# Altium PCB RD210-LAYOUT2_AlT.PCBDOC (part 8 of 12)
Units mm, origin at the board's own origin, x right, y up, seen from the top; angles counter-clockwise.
Board outline 250 x 123 mm, 4 copper layers (TOP, Mid-Layer 1, Mid-Layer 2, BOTTOM), stack 0.711 mm thick; 1043 components, 659 nets, 2786 pads, 1228 vias.
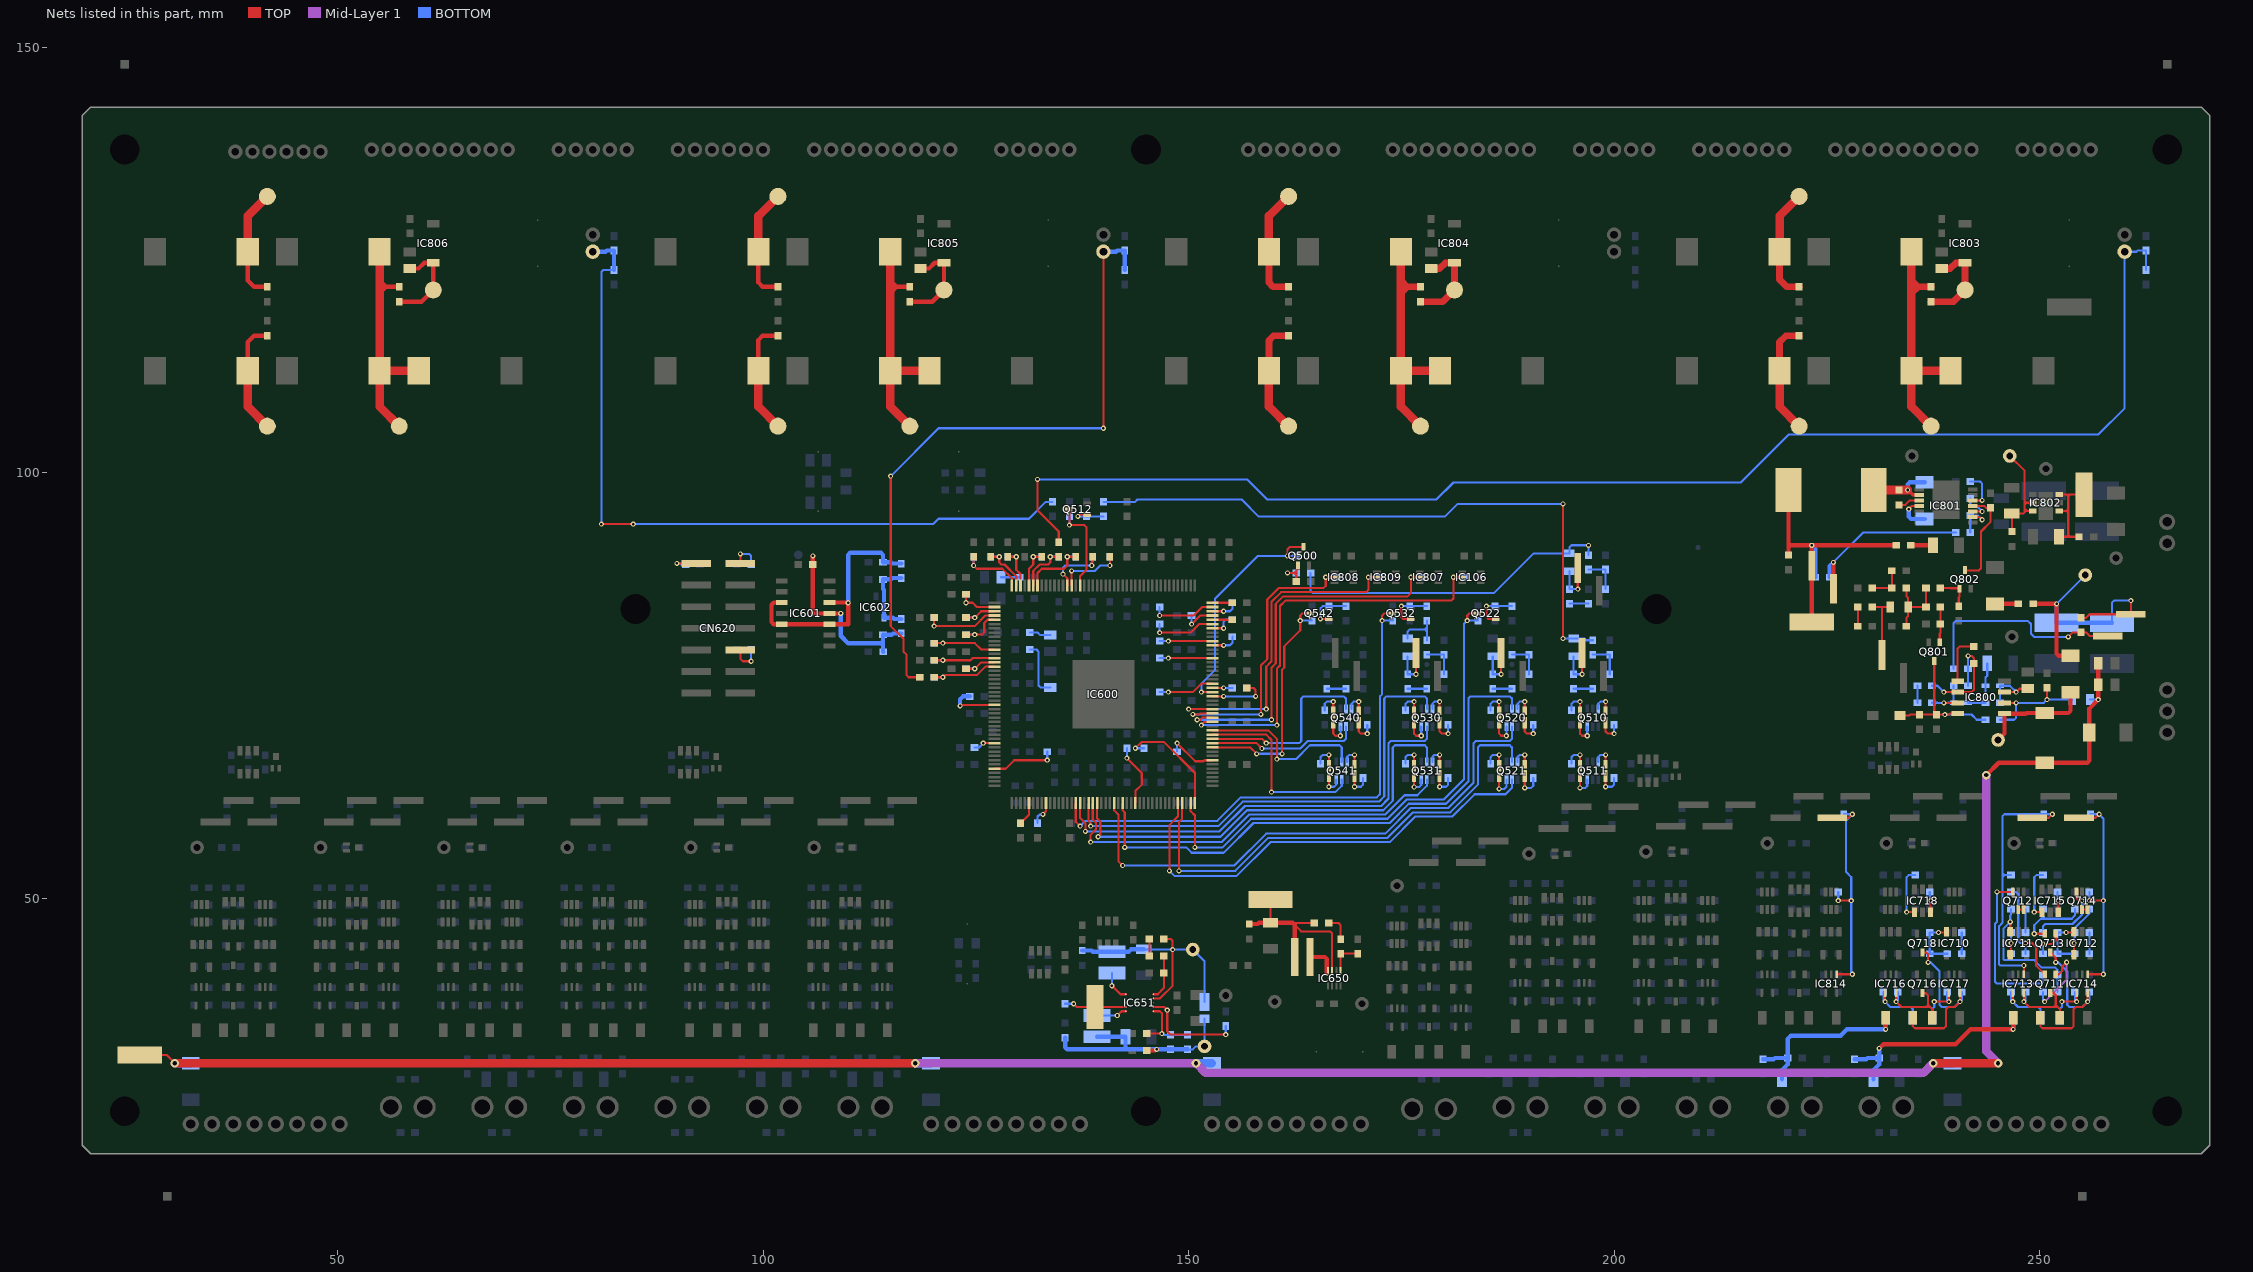
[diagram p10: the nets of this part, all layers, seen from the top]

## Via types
v1: diameter 0.6, hole 0.3, TOP to BOTTOM, 1134 vias
v2: diameter 1, hole 0.5, TOP to BOTTOM, 94 vias

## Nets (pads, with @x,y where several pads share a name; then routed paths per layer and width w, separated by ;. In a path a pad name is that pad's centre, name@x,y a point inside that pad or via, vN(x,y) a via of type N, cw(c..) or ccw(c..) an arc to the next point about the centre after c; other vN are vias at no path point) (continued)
N00100041: Q542.1 R597.2 R598.2 | length 5.3
  TOP w0.25: v1(165.5,82.85) Q542.1@166.425,82.85
  BOTTOM w0.25: v1(165.5,82.85) 165.5,84.1 165.75,84.35 R598.2@166.5,84.35 R597.2@168.5,84.35
N00100042: C520.2 IC600.42 R520.1 | length 5.6
  TOP w0.25: R520.1@128.75,90.15 v1(129.75,90.15) 129.75,88.625 130.25,88.125 IC600.42@130.25,86.8
  BOTTOM w0.25: C520.2@128.75,90.15 v1(129.75,90.15)
N00100043: C521.1 IC600.47 R521.2 | length 4.7
  TOP w0.25: R521.2@123.85,83 v1(124.875,83) 125.625,83.75 IC600.47@127.2,83.75
  BOTTOM w0.25: C521.1@123.85,83 v1(124.875,83)
N00100044: C532.2 IC600.31 R532.2 | length 7.9
  TOP w0.25: v1(135.25,88.125) 135.75,87.625 IC600.31@135.75,86.8 ; v1(138.625,89.125) 138.625,89.5 138.75,89.625 R532.2@138.75,90.15
  BOTTOM w0.25: v1(135.25,88.125) 135.25,88.875 135.5,89.125 v1(138.625,89.125) 138.625,89.5 138.75,89.625 C532.2@138.75,90.15
N00100045: C533.1 IC600.58 R533.2 | length 8.2
  TOP w0.25: R533.2@120.1,78 v1(121.125,78) 124.375,78 124.625,78.25 IC600.58@127.2,78.25
  BOTTOM w0.25: C533.1@120.1,78 v1(121.125,78)
N00100047: C531.1 IC600.48 R531.2 | length 9.6
  TOP w0.25: R531.2@120.1,83 v1(120.1,82) 124.875,82 126.125,83.25 IC600.48@127.2,83.25
  BOTTOM w0.25: v1(120.1,82) C531.1@120.1,83
N00100048: C542.2 IC600.30 R542.2 | length 8.5
  TOP w0.25: IC600.30@136.25,86.8 v1(136.25,88.5) ; v1(140.75,89.125) R542.2@140.75,90.15
  BOTTOM w0.25: v1(136.25,88.5) 139,88.5 139.625,89.125 v1(140.75,89.125) C542.2@140.75,90.15
N00100049: C543.1 IC600.59 R543.2 | length 4.7
  TOP w0.25: R543.2@123.85,77 v1(124.875,77) 125.625,77.75 IC600.59@127.2,77.75
  BOTTOM w0.25: C543.1@123.85,77 v1(124.875,77)
N00100050: C540.2 IC600.40 R540.1 | length 5.6
  TOP w0.25: IC600.40@131.25,86.8 131.25,88.75 131.75,89.25 v1(131.75,90.15) R540.1@132.75,90.15
  BOTTOM w0.25: v1(131.75,90.15) C540.2@132.75,90.15
N00100051: C541.1 IC600.49 R541.2 | length 5.8
  TOP w0.25: R541.2@123.85,81 v1(124.875,81) 125.75,81 126,81.25 126,82.375 126.375,82.75 IC600.49@127.2,82.75
  BOTTOM w0.25: C541.1@123.85,81 v1(124.875,81)
N00100052: C511.1 IC600.46 R511.2 | length 5.6
  TOP w0.25: R511.2@123.85,85.75 v1(123.85,84.75) 124.625,84.75 125.125,84.25 IC600.46@127.2,84.25
  BOTTOM w0.25: v1(123.85,84.75) C511.1@123.85,85.75
N00100053: C510.2 IC600.43 R510.1 | length 6.4
  TOP w0.25: R510.1@126.75,90.15 v1(127.75,90.15) 127.75,89.5 128,89.25 128.375,89.25 129.75,87.875 IC600.43@129.75,86.8
  BOTTOM w0.25: C510.2@126.75,90.15 v1(127.75,90.15)
N00100055: C513.1 IC600.56 R513.2 | length 8.4
  TOP w0.25: R513.2@120.1,80 v1(121.125,80) 124.875,80 125.625,79.25 IC600.56@127.2,79.25
  BOTTOM w0.25: C513.1@120.1,80 v1(121.125,80)
N00100057: C512.2 IC600.44 R512.1 | length 8
  TOP w0.25: R512.1@124.75,90.15 v1(124.75,89.125) 125.125,88.75 128.125,88.75 129.25,87.625 IC600.44@129.25,86.8
  BOTTOM w0.25: v1(124.75,89.125) C512.2@124.75,90.15
N00100061: C544.2 CN305.1 R592.2 R593.1 | length 90.2
  TOP w0.25: v1(81,94) v1(84.75,94)
  BOTTOM w0.25: v1(81,94) 81,123.625 81.225,123.85 R592.2@82.5,123.85 ; v1(84.75,94) 120,94 120.625,94.625 131.25,94.625 133.225,96.6 R593.1@134,96.6
  BOTTOM w0.5: CN305.1@80,126 81.475,126 81.625,126.15 C544.2@82.5,126.15 R592.2@82.5,123.85
N00100071: IC600.69 R613.1 | length 6.1
  TOP w0.25: v1(123.15,72.625) 123.275,72.75 IC600.69@127.2,72.75
  BOTTOM w0.5: v1(123.15,72.625) 123.15,73.4 123.5,73.75 R613.1@124.275,73.75
N00100083: IC600.142 Q542.3 R599.1 | length 28.3
  TOP w0.25: IC600.142@152.8,67.75 157.25,67.75 v1(158,67) ; v1(161,67) 161,76.875 161.25,77.125 161.25,79.625 163.125,81.5 v1(163.125,82.65) 163.125,83.25 163.375,83.5 Q542.3@164.275,83.5 Q542.3@164.325,83.5
  BOTTOM w0.25: v1(158,67) v1(161,67) ; v1(163.125,82.65) R599.1@164.5,82.65
N00100086: DS511.2 Q510.3 | length 3.1
  TOP w0.25: DS511.2@196,70.45 196,69.375 196.25,69.125 v1(196.85,69.125)
  BOTTOM w0.25: v1(196.85,69.125) Q510.3@196.85,70.225
N00100087: IC106.2 IC600.148 R648.1 | length 50
  TOP w0.25: v1(151.5,70.375) 151.875,70.75 IC600.148@152.8,70.75 ; v1(160.375,70.375) 160.375,77 160.75,77.375 160.75,84.375 161.375,85 180.875,85 181.125,85.25 v1(181.125,87.75) IC106.2@182.15,87.75
  BOTTOM w0.25: v1(151.5,70.375) v1(160.375,70.375) ; v1(181.125,87.75) R648.1@182.4,87.75
N00100091: C546.1 C547.2 | length 2.3
  BOTTOM w0.25: C546.1@166.25,74.65 C547.2@168.5,74.65
N00100092: C500.2 CN500.1 R501.1 | length 5.6
  TOP w0.25: CN500.1@195.73,88.85 195.73,86.37 v1(195.75,86.35)
  BOTTOM w0.25: R501.1@194.75,88.45 C500.2@194.75,86.35 v1(195.75,86.35)
N00100094: IC600.93 R618.1 | length 2.8
  TOP w0.25: R618.1@130.25,58.85 131.25,59.85 IC600.93@131.25,61.2
N00100095: CN620.13 R657.1 | length 3.5
  TOP w0.25: CN620.13@97.34,89.37 v1(97.34,90.5)
  BOTTOM w0.25: v1(97.34,90.5) 98.35,90.5 98.6,90.25 R657.1@98.6,89.25
N00100096: R564.2 R566.1 R567.1 | length 75
  TOP w0.25: v1(194,80.55) v1(194,96.375)
  BOTTOM w0.25: R567.1@140,96.6 143.725,96.6 144,96.875 156.25,96.875 158.25,94.875 180.125,94.875 181.625,96.375 v1(194,96.375) ; v1(194,80.55) R564.2@195.25,80.55 196.5,80.55 196.7,80.35 R566.1@197.5,80.35
N00100097: C526.2 CN520.1 R574.1 | length 5.6
  TOP w0.25: v1(186.73,76.35) CN520.1@186.73,78.85
  BOTTOM w0.25: R574.1@185.75,78.45 C526.2@185.75,76.35 v1(186.73,76.35)
N00100098: IC600.97 R508.1 | length 3
  TOP w0.25: v1(132.875,59.875) 133.25,60.25 IC600.97@133.25,61.2
  BOTTOM w0.25: R508.1@132.25,58.85 132.25,59.625 132.5,59.875 v1(132.875,59.875)
N00100100: IC600.163 R601.2 | length 6.2
  TOP w0.25: v1(147.625,78.25) IC600.163@152.8,78.25
  BOTTOM w0.25: R601.2@146.6,78.25 v1(147.625,78.25)
N00100113: C516.1 C517.2 | length 2.3
  BOTTOM w0.25: C516.1@195.25,74.65 C517.2@197.5,74.65
N00100114: R501.2 R503.1 R504.1 | length 38.8
  BOTTOM w0.25: R504.1@164.35,88.25 164.35,86.125 164.6,85.875 185.875,85.875 190.55,90.55 R501.2@194.75,90.55 194.75,91.25 195,91.5 v1(197,91.5) R503.1@197,90.35
N00100116: IC600.115 Q520.5 | length 65.7
  TOP w0.25: IC600.115@142.25,61.2 142.25,60.35 142.5,60.1 v1(142.5,56)
  BOTTOM w0.25: v1(142.5,56) 149.75,56 150.375,55.375 154.125,55.375 157.625,58.875 173.625,58.875 175.875,61.125 180.25,61.125 182.875,63.75 182.875,73.5 183.125,73.75 187.75,73.75 188,73.5 Q520.5@188,72.275
N00100117: IC600.166 R602.2 | length 3.2
  TOP w0.25: IC600.166@152.8,79.75 v1(154.125,79.75)
  BOTTOM w0.25: v1(154.125,79.75) 154.875,79.75 155.15,80.025 R602.2@155.15,80.75
N00100118: C516.2 CN510.1 R564.1 | length 5.6
  TOP w0.25: CN510.1@196.23,78.85 196.23,76.37 v1(196.25,76.35)
  BOTTOM w0.25: R564.1@195.25,78.45 C516.2@195.25,76.35 v1(196.25,76.35)
N00100120: C518.2 R565.1 R566.2 | length 4.3
  BOTTOM w0.25: R566.2@197.5,78.65 R565.1@199.5,78.65 C518.2@199.5,76.35
N00100121: Q512.1 R567.2 R568.2 | length 4.1
  TOP w0.25: v1(137,94.9) 137.2,95.1 Q512.1@138.05,95.1
  BOTTOM w0.25: v1(137,94.9) R568.2@138,94.9 R567.2@140,94.9
N00100122: C526.1 C527.2 | length 2.2
  BOTTOM w0.25: C526.1@185.75,74.65 C527.2@188,74.65
N00100123: C535.1 IC600.60 R583.1 | length 8.6
  TOP w0.25: R583.1@120.1,76 v1(121.125,76) 121.375,76.25 125.125,76.25 126.125,77.25 IC600.60@127.2,77.25
  BOTTOM w0.25: C535.1@120.1,76 v1(121.125,76)
N00100124: IC600.28 Q512.3 R569.1 | length 12.2
  TOP w0.25: Q512.3@135.95,95.75 136,95.7 v1(136,93.875) 137.75,93.875 138,93.625 138,88.625 137.25,87.875 IC600.28@137.25,86.8
  BOTTOM w0.25: v1(136,93.875) R569.1@136,94.9
N00100130: C525.2 IC600.38 R573.2 | length 8.3
  TOP w0.25: IC600.38@132.25,86.8 132.25,88.25 132.75,88.75 135.375,88.75 135.75,89.125 v1(135.75,90.15) R573.2@136.75,90.15
  BOTTOM w0.25: v1(135.75,90.15) C525.2@136.75,90.15
N00100131: C528.2 R575.1 R576.2 | length 4.3
  BOTTOM w0.25: R576.2@188,78.65 R575.1@190,78.65 C528.2@190,76.35
N00100132: Q522.1 R577.2 R578.2 | length 5.4
  TOP w0.25: v1(185,84.35) 185,83.1 185.25,82.85 Q522.1@186.05,82.85
  BOTTOM w0.25: v1(185,84.35) R578.2@186,84.35 R577.2@188,84.35
N00100133: IC600.132 R624.1 | length 13.4
  TOP w0.25: v1(143.75,67.65) 144.475,68.375 147.125,68.375 150.75,64.75 IC600.132@150.75,61.2
  BOTTOM w0.25: v1(143.75,67.65) R624.1@144.75,67.65
N00100135: IC600.84 R507.1 | length 7.6
  TOP w0.25: IC600.84@127.2,65.25 128.5,65.25 129.5,66.25 v1(133.4,66.25)
  BOTTOM w0.25: v1(133.4,66.25) R507.1@133.4,67.25
N00100137: IC600.167 R603.2 | length 6.2
  TOP w0.25: v1(147.625,80.25) IC600.167@152.8,80.25
  BOTTOM w0.25: R603.2@146.6,80.25 v1(147.625,80.25)
N00100141: CN620.14 R658.1 | length 3.4
  TOP w0.25: v1(89.875,89.37) CN620.14@92.16,89.37
  BOTTOM w0.25: v1(89.875,89.37) 90.255,89.37 90.375,89.25 R658.1@90.9,89.25
N00100148: IC600.104 Q532.3 R589.1 | length 63.4
  TOP w0.25: IC600.104@136.75,61.2 136.75,59 v1(137.25,58.5) ; v1(172.75,82.65) 172.75,83.25 173,83.5 Q532.3@173.9,83.5 Q532.3@173.95,83.5
  BOTTOM w0.25: v1(137.25,58.5) 137.875,59.125 153.375,59.125 156.125,61.875 172.125,61.875 172.5,62.25 172.5,73.75 172.75,74 v1(172.75,82.65) R589.1@174,82.65
N00100149: CN620.5 R656.1 | length 3.8
  TOP w0.25: CN620.5@97.34,79.21 97.34,78.16 97.625,77.875 v1(98.6,77.875)
  BOTTOM w0.25: v1(98.6,77.875) R656.1@98.6,79.25
N00100151: R584.1 R586.1 R587.2 | length 5.9
  BOTTOM w0.25: R584.1@175.75,80.55 175.75,81.375 176,81.625 177.75,81.625 ; R586.1@178,80.35 178,81.375 ; R587.2@178,82.65 178,81.875 ; 177.75,81.625 178,81.375 ; 177.75,81.625 178,81.875 ; 178,81.375 178,81.875
N00100154: C536.2 CN530.1 R584.2 | length 5.6
  TOP w0.25: v1(176.73,76.35) CN530.1@176.73,78.85
  BOTTOM w0.25: R584.2@175.75,78.45 C536.2@175.75,76.35 v1(176.73,76.35)
N00100157: C536.1 C537.2 | length 2.2
  BOTTOM w0.25: C536.1@175.75,74.65 C537.2@178,74.65
N00100158: C538.2 R585.1 R586.2 | length 4.3
  BOTTOM w0.25: R586.2@178,78.65 R585.1@180,78.65 C538.2@180,76.35
N00100161: IC600.118 R647.1 | length 7.5
  TOP w0.25: v1(142.75,66.5) 144.5,64.75 144.5,63.375 143.75,62.625 IC600.118@143.75,61.2
  BOTTOM w0.25: v1(142.75,66.5) R647.1@142.75,67.65
N00100162: IC600.108 Q531.2 | length 48
  TOP w0.25: v1(138.5,56.625) 138.5,57.5 139.125,58.125 139.125,58.9 138.75,59.275 IC600.108@138.75,61.2
  BOTTOM w0.25: v1(138.5,56.625) 153.875,56.625 157.125,59.875 173.125,59.875 175.375,62.125 176.875,62.125 178,63.25 Q531.2@178,63.975
N00100163: DS530.2 Q530.6 | length 2.6
  TOP w0.25: DS530.2@179.5,72.05 v1(179.5,73.125)
  BOTTOM w0.25: Q530.6@178.65,72.275 178.65,72.875 178.9,73.125 v1(179.5,73.125)
N00100164: DS533.2 Q531.3 | length 2.7
  TOP w0.25: v1(176.5,63.1) DS533.2@176.5,64.2
  BOTTOM w0.25: v1(176.5,63.1) 177.1,63.1 177.35,63.35 Q531.3@177.35,63.975
N00100165: DS531.2 Q530.3 | length 3.1
  TOP w0.25: DS531.2@176.5,70.45 176.5,69.375 176.75,69.125 v1(177.35,69.125)
  BOTTOM w0.25: v1(177.35,69.125) Q530.3@177.35,70.225
N00100166: IC600.109 Q531.5 | length 52.8
  TOP w0.25: IC600.109@139.25,61.2 139.25,59.425 139.625,59.05 139.625,57.5 v1(139.375,57.25)
  BOTTOM w0.25: v1(139.375,57.25) 153.75,57.25 156.875,60.375 172.875,60.375 174,61.5 174,67.75 174.25,68 177.75,68 178,67.75 Q531.5@178,66.025
N00100168: IC600.105 Q530.2 | length 53.5
  TOP w0.25: IC600.105@137.25,61.2 137.25,59.475 137.875,58.85 v1(137.875,57.875)
  BOTTOM w0.25: v1(137.875,57.875) 153.625,57.875 156.625,60.875 172.625,60.875 173.5,61.75 173.5,68.25 173.75,68.5 177.75,68.5 178,68.75 Q530.2@178,70.225
N00100169: IC600.107 Q530.5 | length 56.7
  TOP w0.25: IC600.107@138.25,61.2 138.25,59.125 138.5,58.875 v1(138.5,58.5)
  BOTTOM w0.25: v1(138.5,58.5) 153.5,58.5 156.375,61.375 172.375,61.375 173,62 173,73.5 173.25,73.75 177.75,73.75 178,73.5 Q530.5@178,72.275
N00100170: DS532.2 Q531.6 | length 2.6
  TOP w0.25: DS532.2@179.5,65.8 v1(179.5,66.875)
  BOTTOM w0.25: Q531.6@178.65,66.025 178.65,66.625 178.9,66.875 v1(179.5,66.875)
N00100172: DS530.1 R536.1 | length 3.2
  TOP w0.25: DS530.1@179.5,70.65 179.5,69.625 179.75,69.375 v1(180.5,69.375)
  BOTTOM w0.25: v1(180.5,69.375) R536.1@180.5,70.4
N00100176: Q532.1 R587.1 R588.2 | length 5.4
  TOP w0.25: v1(175,84.35) 175,83.1 175.25,82.85 Q532.1@176.05,82.85
  BOTTOM w0.25: v1(175,84.35) R588.2@176,84.35 R587.1@178,84.35
N00100178: C514.2 CN5.1 R562.2 R563.1 | length 164.9
  TOP w0.25: v1(132.25,99.25) 132.25,95.625 134.75,93.125 R563.1@134.75,91.85
  BOTTOM w0.25: v1(132.25,99.25) 156.875,99.25 159.25,96.875 179.125,96.875 181.125,98.875 214.875,98.875 220.5,104.5 256.875,104.5 260,107.625 CN5.1@260,126 261.375,126 261.525,126.15 C514.2@262.5,126.15 R562.2@262.5,123.85
N00100181: C515.2 IC600.39 R563.2 | length 6.8
  TOP w0.25: IC600.39@131.75,86.8 131.75,88.5 132.5,89.25 133.5,89.25 133.75,89.5 v1(133.75,90.15) R563.2@134.75,90.15
  BOTTOM w0.25: v1(133.75,90.15) C515.2@134.75,90.15
N00100182: DS533.1 R539.1 | length 3.2
  TOP w0.25: DS533.1@176.5,65.6 v1(176.5,66.875)
  BOTTOM w0.25: R539.1@175.5,65.85 175.5,66.625 175.75,66.875 v1(176.5,66.875)
N00100185: DS531.1 R537.1 | length 3.2
  TOP w0.25: DS531.1@176.5,71.85 v1(176.5,73.125)
  BOTTOM w0.25: R537.1@175.5,72.1 175.5,72.875 175.75,73.125 v1(176.5,73.125)
N00100187: DS510.1 R516.1 | length 3.2
  TOP w0.25: DS510.1@199,70.65 199,69.625 199.25,69.375 v1(200,69.375)
  BOTTOM w0.25: v1(200,69.375) R516.1@200,70.4
N00100190: DS510.2 Q510.6 | length 2.6
  TOP w0.25: DS510.2@199,72.05 v1(199,73.125)
  BOTTOM w0.25: Q510.6@198.15,72.275 198.15,72.875 198.4,73.125 v1(199,73.125)
N00100191: DS532.1 R538.1 | length 3.2
  TOP w0.25: v1(179.5,63.125) DS532.1@179.5,64.4
  BOTTOM w0.25: v1(179.5,63.125) 180.25,63.125 180.5,63.375 R538.1@180.5,64.15
N00100192: DS511.1 R517.1 | length 3.2
  TOP w0.25: DS511.1@196,71.85 v1(196,73.125)
  BOTTOM w0.25: R517.1@195,72.1 195,72.875 195.25,73.125 v1(196,73.125)
N00100193: IC600.145 Q541.2 | length 22.6
  TOP w0.25: IC600.145@152.8,69.25 159.125,69.25 159.75,68.625 v1(159.75,62.5)
  BOTTOM w0.25: v1(159.75,62.5) 167.25,62.5 168,63.25 Q541.2@168,63.975
N00100197: C534.2 CN205.1 R582.2 R583.2 | length 78.7
  TOP w0.25: v1(115,99.625) 115,82 116.5,80.5 116.5,79 116.875,78.625 116.875,76.25 117.125,76 R583.2@118.4,76 ; v1(140,105.25) CN205.1@140,126
  BOTTOM w0.25: v1(115,99.625) 120.625,105.25 v1(140,105.25)
  BOTTOM w0.5: CN205.1@140,126 141.475,126 141.625,126.15 C534.2@142.5,126.15 R582.2@142.5,123.85
N00100198: C502.2 R502.1 R503.2 | length 4.3
  BOTTOM w0.25: R503.2@197,88.65 R502.1@199,88.65 C502.2@199,86.35
N00100199: IC600.146 Q541.5 | length 20.5
  TOP w0.25: IC600.146@152.8,69.75 159.375,69.75 160.375,68.75 v1(160.375,66.375)
  BOTTOM w0.25: v1(160.375,66.375) 162.625,66.375 164.25,68 167.75,68 168,67.75 Q541.5@168,66.025
N00100200: DS512.1 R518.1 | length 3.2
  TOP w0.25: v1(199,63.125) DS512.1@199,64.4
  BOTTOM w0.25: v1(199,63.125) 199.75,63.125 200,63.375 R518.1@200,64.15
N00100201: DS512.2 Q511.6 | length 2.6
  TOP w0.25: DS512.2@199,65.8 v1(199,66.875)
  BOTTOM w0.25: Q511.6@198.15,66.025 198.15,66.625 198.4,66.875 v1(199,66.875)
N00100203: IC600.143 Q540.2 | length 17.9
  TOP w0.25: IC600.143@152.8,68.25 158,68.25 v1(158.625,67.625)
  BOTTOM w0.25: v1(158.625,67.625) 163.125,67.625 164,68.5 168.25,68.5 168.5,68.75 Q540.2@168.5,70.225
N00100204: DS541.2 Q540.3 | length 3.1
  TOP w0.25: DS541.2@167,70.45 167,69.375 167.25,69.125 v1(167.85,69.125)
  BOTTOM w0.25: v1(167.85,69.125) Q540.3@167.85,70.225
N00100205: DS513.1 R519.1 | length 3.2
  TOP w0.25: DS513.1@196,65.6 v1(196,66.875)
  BOTTOM w0.25: R519.1@195,65.85 195,66.625 195.25,66.875 v1(196,66.875)
N00100206: DS542.2 Q541.6 | length 2.6
  TOP w0.25: DS542.2@169.5,65.8 v1(169.5,66.875)
  BOTTOM w0.25: Q541.6@168.65,66.025 168.65,66.65 168.875,66.875 v1(169.5,66.875)
N00100209: DS513.2 Q511.3 | length 2.9
  TOP w0.25: v1(196,63) DS513.2@196,64.2
  BOTTOM w0.25: v1(196,63) 196.625,63 196.85,63.225 Q511.3@196.85,63.975
N00100214: DS540.2 Q540.6 | length 2.6
  TOP w0.25: DS540.2@170,72.05 v1(170,73.125)
  BOTTOM w0.25: Q540.6@169.15,72.275 169.15,72.875 169.4,73.125 v1(170,73.125)
N00100215: IC600.144 Q540.5 | length 22.4
  TOP w0.25: IC600.144@152.8,68.75 158.625,68.75 v1(159.125,68.25)
  BOTTOM w0.25: v1(159.125,68.25) 163,68.25 163.25,68.5 163.25,73.5 163.5,73.75 168.25,73.75 168.5,73.5 Q540.5@168.5,72.275
N00100217: DS543.2 Q541.3 | length 2.6
  TOP w0.25: v1(166.5,63.125) DS543.2@166.5,64.2
  BOTTOM w0.25: v1(166.5,63.125) 167.1,63.125 167.35,63.375 Q541.3@167.35,63.975
N00100219: IC600.149 IC807.2 R635.1 | length 45.1
  TOP w0.25: v1(151,71) 151.375,71 151.625,71.25 IC600.149@152.8,71.25 ; v1(159.75,71) 159.75,77.125 160.25,77.625 160.25,84.625 161.125,85.5 175.75,85.5 176.125,85.875 v1(176.125,87.75) IC807.2@177.15,87.75
  BOTTOM w0.25: v1(151,71) v1(159.75,71) ; v1(176.125,87.75) R635.1@177.4,87.75
N00100220: DS542.1 R548.1 | length 3.2
  TOP w0.25: v1(169.5,63.125) DS542.1@169.5,64.4
  BOTTOM w0.25: v1(169.5,63.125) 170.25,63.125 170.5,63.375 R548.1@170.5,64.15
N00100224: DS540.1 R546.1 | length 3.2
  TOP w0.25: DS540.1@170,70.65 170,69.625 170.25,69.375 v1(171,69.375)
  BOTTOM w0.25: v1(171,69.375) R546.1@171,70.4
N00100226: DS543.1 R549.1 | length 3.2
  TOP w0.25: DS543.1@166.5,65.6 v1(166.5,66.875)
  BOTTOM w0.25: R549.1@165.5,65.85 165.5,66.625 165.75,66.875 v1(166.5,66.875)
N00100228: DS541.1 R547.1 | length 3.2
  TOP w0.25: DS541.1@167,71.85 v1(167,73.125)
  BOTTOM w0.25: R547.1@166,72.1 166,72.875 166.25,73.125 v1(167,73.125)
N00100230: C500.1 C501.2 | length 2.3
  BOTTOM w0.25: C500.1@194.75,84.65 C501.2@197,84.65
N00100231: IC600.139 R631.2 | length 6.1
  TOP w0.25: v1(148.65,68.25) 150.775,66.125 151.75,66.125 151.875,66.25 IC600.139@152.8,66.25
  BOTTOM w0.25: R631.2@148.65,67.25 v1(148.65,68.25)
N00100234: DS520.2 Q520.6 | length 2.6
  TOP w0.25: DS520.2@189.5,72.05 v1(189.5,73.125)
  BOTTOM w0.25: Q520.6@188.65,72.275 188.65,72.875 188.9,73.125 v1(189.5,73.125)
N00100236: DS523.2 Q521.3 | length 3.1
  TOP w0.25: v1(186.5,62.875) DS523.2@186.5,64.2
  BOTTOM w0.25: v1(186.5,62.875) 187.125,62.875 187.35,63.1 Q521.3@187.35,63.975
N00100239: IC600.154 R655.2 | length 7
  TOP w0.25: IC600.154@152.8,73.75 v1(154.125,73.75) ; R655.2@156.85,74.75 157.625,74.75 157.875,74.5 v1(157.875,73.75)
  BOTTOM w0.25: v1(154.125,73.75) v1(157.875,73.75)
N00100240: DS521.2 Q520.3 | length 3.1
  TOP w0.25: DS521.2@186.5,70.45 186.5,69.375 186.75,69.125 v1(187.35,69.125)
  BOTTOM w0.25: v1(187.35,69.125) Q520.3@187.35,70.225
N00100241: IC600.156 R638.2 | length 2.4
  TOP w0.25: IC600.156@152.8,74.75 v1(154.125,74.75)
  BOTTOM w0.25: v1(154.125,74.75) R638.2@155.15,74.75
N00100242: IC600.129 Q521.5 | length 57.7
  TOP w0.25: v1(148.875,53.25) 148.875,59 149.25,59.375 IC600.129@149.25,61.2
  BOTTOM w0.25: v1(148.875,53.25) 155.5,53.25 159.375,57.125 173.375,57.125 176.375,60.125 180.75,60.125 184,63.375 184,67.75 184.25,68 187.75,68 188,67.75 Q521.5@188,66.025
N00100243: IC600.157 R639.2 | length 6.6
  TOP w0.25: v1(147.625,74.25) 150.5,74.25 151.5,75.25 IC600.157@152.8,75.25
  BOTTOM w0.25: R639.2@146.6,74.25 v1(147.625,74.25)
N00100245: IC600.170 R640.2 | length 3.2
  TOP w0.25: IC600.170@152.8,81.75 v1(154.125,81.75)
  BOTTOM w0.25: v1(154.125,81.75) 154.125,82.5 154.375,82.75 R640.2@155.15,82.75
N00100246: IC600.113 Q520.2 | length 63.8
  TOP w0.25: IC600.113@141.25,61.2 141.25,60.375 141.75,59.875 141.75,54.375 v1(142.25,53.875)
  BOTTOM w0.25: v1(142.25,53.875) 155.375,53.875 159.125,57.625 173.125,57.625 176.125,60.625 180.5,60.625 183.5,63.625 183.5,68.25 183.75,68.5 187.75,68.5 188,68.75 Q520.2@188,70.225
N00100247: IC600.171 R641.2 | length 7.6
  TOP w0.25: v1(146.6,81.25) 150.25,81.25 151.25,82.25 IC600.171@152.8,82.25
  BOTTOM w0.25: v1(146.6,81.25) R641.2@146.6,82.25
N00100249: IC600.172 R642.2 | length 2.4
  TOP w0.25: IC600.172@152.8,82.75 R642.2@155.15,82.75
N00100250: DS522.2 Q521.6 | length 2.6
  TOP w0.25: DS522.2@189.5,65.8 v1(189.5,66.875)
  BOTTOM w0.25: Q521.6@188.65,66.025 188.65,66.625 188.9,66.875 v1(189.5,66.875)
N00100251: IC600.173 R643.2 | length 3.9
  TOP w0.25: v1(150.35,82.25) 150.375,82.25 151.375,83.25 IC600.173@152.8,83.25
  BOTTOM w0.25: v1(150.35,82.25) R643.2@150.35,83.25
N00100253: IC600.174 R644.2 | length 3.2
  TOP w0.25: IC600.174@152.8,83.75 v1(154.125,83.75)
  BOTTOM w0.25: v1(154.125,83.75) 154.875,83.75 155.15,84.025 R644.2@155.15,84.75
N00100254: DS520.1 R526.1 | length 3.2
  TOP w0.25: DS520.1@189.5,70.65 189.5,69.625 189.75,69.375 v1(190.5,69.375)
  BOTTOM w0.25: v1(190.5,69.375) R526.1@190.5,70.4
N00100255: IC600.175 R634.2 | length 7.6
  TOP w0.25: v1(146.6,83.25) 150.625,83.25 151.625,84.25 IC600.175@152.8,84.25
  BOTTOM w0.25: v1(146.6,83.25) R634.2@146.6,84.25
N00100256: DS523.1 R529.1 | length 3.2
  TOP w0.25: DS523.1@186.5,65.6 v1(186.5,66.875)
  BOTTOM w0.25: R529.1@185.5,65.85 185.5,66.625 185.75,66.875 v1(186.5,66.875)
N00100257: IC600.176 R645.2 | length 2.4
  TOP w0.25: IC600.176@152.8,84.75 R645.2@155.15,84.75
N00100258: DS521.1 R527.1 | length 3.2
  TOP w0.25: DS521.1@186.5,71.85 v1(186.5,73.125)
  BOTTOM w0.25: R527.1@185.5,72.1 185.5,72.875 185.75,73.125 v1(186.5,73.125)
N00100259: DS522.1 R528.1 | length 3.4
  TOP w0.25: v1(189.5,63) DS522.1@189.5,64.4
  BOTTOM w0.25: v1(189.5,63) 190.25,63 190.5,63.25 R528.1@190.5,64.15
N00100262: Q500.1 R504.2 R505.2 | length 4.5
  TOP w0.25: v1(161.625,88.25) 162.4,88.25 ; R505.2@162.65,87.25 162.65,88 ; Q500.1@162.85,89.2 Q500.1@162.85,89.15 162.85,88.7 162.65,88.5 ; 162.4,88.25 162.65,88 ; 162.4,88.25 162.65,88.5 ; 162.65,88 162.65,88.5
  BOTTOM w0.25: v1(161.625,88.25) R504.2@162.65,88.25
N00100265: IC600.78 R659.1 | length 2.6
  TOP w0.25: v1(125.875,68.25) IC600.78@127.2,68.25
  BOTTOM w0.25: R659.1@124.85,67.75 125.375,67.75 v1(125.875,68.25)
N00100271: IC600.155 Q500.3 R500.1 | length 27.3
  TOP w0.25: v1(151.5,74.25) IC600.155@152.8,74.25 ; v1(161.625,90.25) 161.625,91.05 161.875,91.3 Q500.3@163.5,91.3
  BOTTOM w0.25: v1(151.5,74.25) 151.5,75.25 153.125,76.875 153.125,85.25 158.125,90.25 v1(161.625,90.25) R500.1@162.65,90.25
N00100292: IC600.150 IC808.2 R636.1 | length 35
  TOP w0.25: v1(150.5,71.625) 151.25,71.625 151.375,71.75 IC600.150@152.8,71.75 ; v1(158.5,71.625) 158.5,77.375 159.25,78.125 159.25,85.125 160.625,86.5 165.875,86.5 166.125,86.75 v1(166.125,87.75) IC808.2@167.15,87.75
  BOTTOM w0.25: v1(150.5,71.625) v1(158.5,71.625) ; v1(166.125,87.75) R636.1@167.4,87.75
N00100296: IC600.151 IC809.2 R637.1 | length 40.6
  TOP w0.25: v1(150,72.25) IC600.151@152.8,72.25 ; v1(159.125,72.25) 159.125,77.25 159.75,77.875 159.75,84.875 160.875,86 170.875,86 171.125,86.25 v1(171.125,87.75) IC809.2@172.15,87.75
  BOTTOM w0.25: v1(150,72.25) v1(159.125,72.25) ; v1(171.125,87.75) R637.1@172.4,87.75
N00100301: C606.1 R664.2 | length 2.5
  BOTTOM w0.25: R664.2@131.35,81.25 132.25,81.25 132.525,80.975 C606.1@133.75,80.975
N00100303: C604.1 R662.2 | length 6.6
  BOTTOM w0.25: R662.2@131.35,79.25 132.125,79.25 132.375,79 132.375,75.025 132.625,74.775 C604.1@133.75,74.775
N00100304: C607.2 R665.1 | length 2.2
  BOTTOM w0.25: C607.2@127.975,87.75 R665.1@130.15,87.75
N00100314: IC600.128 Q521.2 | length 54.1
  TOP w0.25: v1(147.75,53.25) 147.75,58.625 148.75,59.625 IC600.128@148.75,61.2
  BOTTOM w0.25: v1(147.75,53.25) 148.375,52.625 155.625,52.625 159.625,56.625 173.625,56.625 176.625,59.625 181,59.625 183.625,62.25 187.25,62.25 188,63 Q521.2@188,63.975
N00100317: IC600.131 Q522.3 R579.1 | length 62.3
  TOP w0.25: IC600.131@150.25,61.2 150.25,60.25 150.75,59.75 v1(150.75,56) ; v1(182.75,82.65) 182.75,83.25 183,83.5 Q522.3@183.9,83.5 Q522.3@183.95,83.5
  BOTTOM w0.25: v1(150.75,56) 154,56 157.375,59.375 173.375,59.375 175.625,61.625 180,61.625 182.375,64 182.375,82.275 v1(182.75,82.65) R579.1@184,82.65
N00200002: C806.2 C807.2 D809.1 IC800.7 | length 6.2
  TOP w0.25: v1(238.75,72.99) IC800.7@240.375,72.99
  BOTTOM w0.25: C807.2@237.35,73 238,73 238.01,72.99 v1(238.75,72.99) 239.24,72.99 239.25,73 D809.1@239.9,73 C806.2@239.9,75
N00200008: C807.1 R800.2 | length 2
  BOTTOM w0.25: C807.1@235.65,73 R800.2@235.65,75
N00200022: IC651.9 J829.1 TP806.1 | length 7.3
  TOP w0.25: v1(136.5,37.625) 136.875,37.25 TP806.1@139,37.25 IC651.9@142.625,37.25
  BOTTOM w0.25: J829.1@135.5,37.625 v1(136.5,37.625)
N00200052: C802.2 C803.2 D800.2 D801.2 D802.2 D803.2 D804.2 L800.1 R807.2 TP801.1 | length 287.7
  TOP w0.25: TP801.1@26.75,31.625 29.9,31.625 v2(30.875,30.65)
  TOP w0.5: v2(243.75,64.5) 245.2,65.95 L800.1@250.625,65.95 255.6,65.95 255.85,66.2 D800.2@255.85,69.5 255.85,72.325 v1(256.9,73.375) C803.2@256.9,75.125 C802.2@256.9,77.625
  TOP w1: v2(30.875,30.65) v2(117.875,30.65) ; v2(237.5,30.65) v2(245.125,30.65)
  Mid-Layer 1 w1: v2(117.875,30.65) v2(150.875,30.65) 152.025,29.5 236.35,29.5 v2(237.5,30.65) ; v2(243.75,64.5) 243.75,32.025 v2(245.125,30.65)
  BOTTOM w0.25: R807.2@255.925,73.375 v1(256.9,73.375)
  BOTTOM w1: v2(30.875,30.65) D804.2@32.75,30.65 ; v2(117.875,30.65) D803.2@119.75,30.65 ; v2(150.875,30.65) D802.2@152.75,30.65 ; v2(237.5,30.65) D801.2@239.75,30.65
N00200060: D807.1 IC801.4 | length 4.2
  TOP w0.25: v1(234.625,95.75) 235,96.125 IC801.4@235.85,96.125
  BOTTOM w0.5: v1(234.625,95.75) 234.625,94.875 234.9,94.6 D807.1@236.5,94.6
N00200068: C809.2 D810.2 IC800.3 R801.1 | length 7.1
  TOP w0.25: IC800.3@245.875,74.26 v1(247.25,74.26) 247.64,74.65 C809.2@248.625,74.65
  BOTTOM w0.25: R801.1@245.35,73 D810.2@245.35,75 246.51,75 v1(247.25,74.26)
N00200070: IC800.5 R805.2 | length 5.8
  TOP w0.25: IC800.5@240.375,75.53 240.375,79.375 240.625,79.625 R805.2@242.275,79.625
N00200079: C804.2 IC800.2 R806.1 R807.1 | length 13.3
  TOP w0.25: IC800.2@245.875,72.99 v1(247.25,72.99) ; v1(250.875,73.375) C804.2@250.875,74.775
  BOTTOM w0.25: R806.1@245.35,71 247,71 247.25,71.25 v1(247.25,72.99) 250.49,72.99 v1(250.875,73.375) R807.1@253.825,73.375
N00200080: CN952.1 D806.1 IC800.1 L800.2 | length 13.5
  TOP w0.5: CN952.1@245.125,68.625 245.875,69.375 IC800.1@245.875,71.72 248.375,71.72 248.455,71.8 L800.2@250.625,71.8 253.375,71.8 253.625,72.05 D806.1@253.625,74.225
N00200081: C805.1 D808.2 IC800.8 Q801.3 R804.1 R806.2 | length 18.4
  TOP w0.25: D808.2@233.425,71.5 D808.2@233.6,71.5 234.675,71.5 234.775,71.6 R804.1@235.875,71.6 C805.1@237.625,71.6 ; Q801.3@237.625,77.95 Q801.3@237.625,77.9 C805.1@237.625,71.6 ; IC800.8@240.375,71.72 239.5,71.72 239.38,71.6 v1(238.875,71.6) C805.1@237.875,71.6 C805.1@237.625,71.6
  BOTTOM w0.25: v1(238.875,71.6) 238.9,71.625 242,71.625 242.625,71 R806.2@243.65,71
N00200084: C806.1 IC800.6 R800.1 R808.1 R809.2 | length 13.4
  TOP w0.25: v1(238.75,74.26) IC800.6@240.375,74.26 242.025,74.26 242.275,74.51 R809.2@242.275,77.625 242.275,78.25 242.025,78.5 v1(241.6,78.5)
  BOTTOM w0.25: R800.1@237.35,75 238.01,75 v1(238.75,74.26) ; C806.1@241.6,75 R808.1@241.6,77 v1(241.6,78.5)
N00200089: CN945.2 R808.2 R900.1 | length 25.4
  TOP w0.25: v1(253.375,80.73) 253.92,81.275 R900.1@254.875,81.275 255.455,81.275 255.875,80.855 CN945.2@258.025,80.855
  BOTTOM w0.25: R808.2@239.9,77 239.9,82.375 240.15,82.625 248.625,82.625 249,82.25 249,81.125 249.395,80.73 v1(253.375,80.73)
N00200092: C808.2 D809.2 D810.1 R801.2 | length 6.8
  BOTTOM w0.25: D809.2@241.6,73 R801.2@243.65,73 D810.1@243.65,75 243.65,75.975 243.85,76.175 C808.2@243.85,77.625
N00200097: C815.2 D807.2 IC801.2 L801.1 | length 8.3
  TOP w0.4: v1(234.5,98) 235.075,97.425 IC801.2@235.85,97.425
  TOP w1: L801.1@230.5,98 C815.2@233.5,98 v1(234.5,98)
  BOTTOM w0.5: v1(234.5,98) 234.5,98.65 234.75,98.9 D807.2@236.5,98.9
N00200108: C820.2 R802.1 R810.1 R816.2 R818.1 | length 9
  TOP w0.25: C820.2@234.35,82 234.35,83 234.55,83.2 R816.2@234.55,84.25 ; R818.1@234.35,86.5 234.35,85.5 234.55,85.3 R816.2@234.55,84.25 ; R810.1@236.65,86.5 R802.1@236.65,84.25 R816.2@234.55,84.25
N00200117: Q802.1 R810.2 R811.2 | length 4.4
  TOP w0.25: R810.2@238.35,86.5 239.5,86.5 239.55,86.45 240.6,86.45 Q802.1@240.6,86.4 240.6,85.475 240.5,85.375 R811.2@240.5,84.35
N00200118: C818.2 R813.1 | length 2.6
  TOP w0.5: R813.1@234.85,91.5 C818.2@237.475,91.5
N00200120: IC801.9 R814.1 R815.2 | length 4.8
  TOP w0.25: IC801.9@242.15,94.825 242.925,94.825 v1(243.25,94.5)
  BOTTOM w0.25: R814.1@241.85,93 R815.2@241.85,95 242.75,95 v1(243.25,94.5)
N00200121: C817.2 IC801.12 | length 4.6
  TOP w0.25: IC801.12@242.15,96.775 v1(243.25,96.775)
  BOTTOM w0.25: C817.2@241.85,99 243,99 243.25,98.75 v1(243.25,96.775)
N00200123: C600.2 C603.2 IC601.4 J827.2 R660.2 | length 22.7
  TOP w0.5: v1(105.85,90.25) C603.2@105.85,89.25 105.85,83.5 IC601.4@107.8,83.5 v1(109.125,83.5)
  BOTTOM w0.5: v1(109.125,83.5) 109.125,80.875 110,80 113.85,80 ; J827.2@114.125,79 114.1,79.025 114.1,79.75 ; R660.2@116.25,81.15 115.275,81.15 115.125,81 C600.2@114.1,81 114.1,80.25 ; 113.85,80 114.1,80.25 ; 113.85,80 114.1,79.75 ; 114.1,79.75 114.1,80.25
N00200124: C815.1 IC801.3 | length 2.6
  TOP w0.25: C815.1@233.5,96.25 234.225,96.25 234.75,96.775 IC801.3@235.85,96.775
N00200125: C813.2 IC801.10 | length 3.6
  TOP w0.25: IC801.10@242.15,95.475 v1(243.25,95.475)
  BOTTOM w0.25: C813.2@241.85,97 241.85,96.25 242.1,96 242.725,96 v1(243.25,95.475)
N00200126: IC801.11 Q802.3 R812.2 | length 11.7
  TOP w0.25: Q802.3@241.25,88.55 242.875,88.55 243.125,88.8 243.125,93.125 244.25,94.25 R812.2@244.25,95.9 243.725,95.9 243.5,96.125 IC801.11@242.15,96.125
N00200127: Q801.1 R802.2 R803.2 | length 4.2
  TOP w0.25: Q801.1@238.275,80.05 Q801.1@238.275,80.1 238.275,81.125 238.35,81.2 R803.2@238.35,82.25 R802.2@238.35,84.25
N00200128: C816.2 CN961.1 IC802.5 IC802.6 J828.2 | length 13.8
  TOP w0.25: CN961.1@246.5,102 248.25,100.25 248.25,96.75 ; J828.2@246.75,93.125 C816.2@246.75,95.225 248.1,95.225 248.25,95.375 ; IC802.6@249.2,95.55 248.5,95.55 248.463,95.587 ; IC802.5@249.2,96.5 248.5,96.5 ; 248.25,95.375 248.463,95.587 ; 248.25,95.375 248.25,95.8 ; 248.25,95.8 248.25,96.25 ; 248.25,95.8 248.463,95.587 ; 248.25,96.25 248.5,96.5 ; 248.25,96.25 248.25,96.75 ; 248.25,96.75 248.5,96.5
N00200129: C819.2 R817.1 R818.2 | length 4.3
  TOP w0.25: C819.2@230.35,86.5 R818.2@232.65,86.5 R817.1@232.65,88.5
N00200130: C800.2 CN400.1 R816.1 | length 7.8
  TOP w0.25: C800.2@230.35,84.25 231.5,84.25 ; CN400.1@231.48,78.6 231.48,84.23 231.5,84.25 ; R816.1@232.45,84.25 231.5,84.25
N00200131: C800.1 C801.2 | length 2.2
  TOP w0.25: C801.2@228.65,82 C800.1@228.65,84.25
N00200135: C810.2 C811.2 CN945.1 CN954.1 D806.2 J818.1 R900.2 | length 36.1
  TOP w0.25: R900.2@254.875,82.975 255.455,82.975 255.875,83.395 CN945.1@260.725,83.395 v1(260.725,85)
  TOP w0.5: J818.1@249.25,84.625 v1(252,84.625) 252,78.775 252.25,78.525 D806.2@253.625,78.525
  BOTTOM w0.25: v1(252,84.625) CN954.1@255.375,88 ; C811.2@258.5,82.4 258.5,84.75 258.75,85 v1(260.725,85)
  BOTTOM w0.5: v1(252,84.625) C810.2@252,82.4 C811.2@258.5,82.4
N00200162: CP6.1 J809.2 L807.1 | length 14.4
  TOP w0.5: 159.45,115.575 159.45,115.625 159.95,116.125 160,116.125
  TOP w0.8: L807.1@159.45,112 159.45,115.575 160,116.125 J809.2@161.75,116.125
  TOP w1: L807.1@159.45,112 159.45,107.8 CP6.1@161.75,105.5
N00200163: IC650.4 L650.1 | length 4
  TOP w0.25: IC650.4@166.25,41.2 IC650.4@166.375,41.2 ; IC650.4@166.25,41.5 IC650.4@166.375,41.5
  TOP w0.5: L650.1@164.265,43.125 166,43.125 166.25,42.875 166.25,41.5 IC650.4@166.25,41.2
N00200164: IC650.1 R671.1 R673.2 | length 4
  TOP w0.25: IC650.1@167.875,41.5 R671.1@167.875,43.525 R673.2@169.875,43.525
N00200166: CP4.1 J814.2 L810.1 L811.1 L812.1 | length 29.7
  TOP w0.8: 234.95,121.125 235.7,121.875 ; 234.95,122.625 235.7,121.875 ; J814.2@237.25,121.875 235.7,121.875
  TOP w1: L810.1@234.95,126 234.95,122.625 234.95,121.125 L811.1@234.95,112 ; CP4.1@237.25,105.5 234.95,107.8 L811.1@234.95,112 ; L812.1@239.55,112 L811.1@234.95,112
N00200167: IC651.6 L656.1 | length 3.5
  TOP w0.25: v1(141,39.75) 142,38.75 IC651.6@142.625,38.75
  BOTTOM w0.25: v1(141,39.75) L656.1@141,41.25
N00200168: C705.2 CN964.1 D650.2 IC651.4 J805.1 L656.2 R676.2 | length 29.2
  TOP w0.25: IC651.4@145.875,38.25 146.625,38.25 148.125,39.75 v1(148.125,44) 148.125,45 147.875,45.25 R676.2@147.1,45.25
  BOTTOM w0.25: C705.2@144.75,44.025 144.775,44 v1(148.125,44) CN964.1@150.5,44 151.875,42.625 D650.2@151.875,37.825
  BOTTOM w0.5: J805.1@137.5,43.875 138.625,43.875 138.75,43.75 L656.2@141,43.75 142.975,43.75 143.25,44.025 C705.2@144.75,44.025
N00200171: IC651.2 R674.2 | length 12.3
  TOP w0.25: IC651.2@145.875,37.25 147.125,37.25 v1(147.5,36.875) 147.5,34.375 147.875,34 v1(154.375,34)
  BOTTOM w0.25: v1(154.375,34) R674.2@154.375,35.025
N00200172: IC651.10 L651.1 | length 3.6
  TOP w0.25: v1(141.625,36.25) 142.125,36.75 IC651.10@142.625,36.75
  BOTTOM w0.25: L651.1@139.25,36.25 v1(141.625,36.25)
N00200173: IC651.5 R675.1 R677.2 | length 5.3
  TOP w0.25: IC651.5@145.875,38.75 146.375,38.75 147.1,39.475 R677.2@147.1,41.25 R675.1@147.1,43.25
N00200175: C601.2 IC602.1 R660.1 R661.1 | length 8.9
  BOTTOM w0.5: R660.1@116.25,82.85 115.4,82.85 115.25,83 IC602.1@114.2,83 114.2,86.275 114.1,86.375 C601.2@114.1,87.5 115,87.5 115.15,87.65 R661.1@116.25,87.65
N00200177: C602.2 IC601.3 IC601.5 IC601.10 IC601.12 R661.2 | length 30
  TOP w0.5: IC601.10@102.1,84.77 101.25,84.77 101,84.52 101,82.48 101.25,82.23 IC601.12@102.2,82.23 IC601.3@107.8,82.23 110,82.23 v1(110,84.75) 110,84.77 IC601.5@107.9,84.77
  BOTTOM w0.5: v1(110,84.75) 110,90.375 110.25,90.625 113.85,90.625 114.1,90.375 C602.2@114.1,89.5 115,89.5 115.15,89.35 R661.2@116.25,89.35
N00200182: C703.2 C704.2 CN963.1 D650.1 J804.1 L651.2 R672.2 R678.2 | length 27.5
  TOP w0.5: R672.2@145.1,32.125 146.1,32.125 v1(146.25,32.275)
  BOTTOM w0.25: C704.2@149.875,32.275 150.5,32.275 150.85,32.625 CN963.1@151.875,32.625 D650.1@151.875,35.875
  BOTTOM w0.5: J804.1@135.5,33.625 135.5,32.525 135.75,32.275 142.35,32.275 ; L651.2@139.25,33.75 C703.2@142.6,33.75 142.6,32.525 ; C704.2@149.875,32.275 R678.2@147.875,32.275 v1(146.25,32.275) 142.85,32.275 ; 142.35,32.275 142.6,32.525 ; 142.35,32.275 142.85,32.275 ; 142.6,32.525 142.85,32.275
N00200184: R670.1 R671.2 | length 3.2
  TOP w0.25: R670.1@166.475,47.125 167.625,47.125 167.875,46.875 R671.2@167.875,45.225
N00200185: CN962.2 R814.2 R819.1 | length 20.9
  TOP w0.5: CN962.2@225.77,86.4 v1(225.77,89.5)
  BOTTOM w0.25: v1(225.77,89.5) 229.27,93 R814.2@240.15,93
  BOTTOM w0.5: R819.1@225.35,87.75 225.35,89.08 v1(225.77,89.5)
N00200188: R675.2 R676.1 | length 2
  TOP w0.25: R675.2@145.4,43.25 R676.1@145.4,45.25
N00200189: C704.1 IC651.1 R678.1 R679.2 | length 8.3
  TOP w0.25: R679.2@145.1,34.125 v1(146.875,34.125) 146.875,36.5 146.625,36.75 IC651.1@145.875,36.75
  BOTTOM w0.25: v1(146.875,34.125) 147.025,33.975 R678.1@147.875,33.975 C704.1@149.875,33.975
N00200197: C652.2 IC650.3 J803.1 L650.2 R670.2 TP804.1 | length 24.1
  TOP w0.25: C652.2@159.625,47.15 TP804.1@159.625,49.875 ; 161.35,47.15 161.375,47.125 ; 162.25,47.125 162.72,47.125 ; R670.2@164.775,47.125 162.72,47.125 ; IC650.3@166.875,41.5 166.875,45.89 166.625,46.14 163.235,46.14 162.485,46.89 162.72,47.125
  TOP w0.5: J803.1@157.125,47 158.125,47 158.275,47.15 C652.2@159.625,47.15 161.35,47.15 162.225,47.15 162.25,47.125 162.485,46.89 L650.2@162.485,43.125
N00200199: C814.1 IC802.1 IC802.3 J801.1 TP802.1 | length 12.7
  TOP w0.25: C814.1@252.275,92.5 253.125,92.5 ; IC802.1@252.3,95.55 253.125,95.55 ; IC802.3@252.3,97.45 253.125,97.45 ; J801.1@254.625,92.5 253.625,92.5 ; TP802.1@255.25,97.45 253.625,97.45 ; 253.125,92.5 253.375,92.75 ; 253.125,92.5 253.625,92.5 ; 253.125,95.55 253.375,95.3 ; 253.125,95.55 253.375,95.8 ; 253.125,97.45 253.375,97.2 ; 253.125,97.45 253.625,97.45 ; 253.375,92.75 253.375,95.3 ; 253.375,92.75 253.625,92.5 ; 253.375,95.3 253.375,95.8 ; 253.375,95.8 253.375,97.2 ; 253.375,97.2 253.625,97.45
N00200201: C829.2 CP3.1 IC803.3 J814.1 | length 10.8
  TOP w0.8: J814.1@237.25,120.125 239.875,120.125 CP3.1@241.25,121.5 IC803.3@241.25,124.7 240.175,124.7 239.5,124.025 C829.2@238.5,124.025
N00200202: CN962.1 J802.1 L801.2 pad.@223.23,91.5 R813.2 R819.2 TP805.1 | length 33.7
  TOP w0.5: J802.1@220.5,90.375 220.5,91.25 ; L801.2@220.5,98 220.5,91.75 ; TP805.1@223.23,82.5 CN962.1@223.23,89.1 v1(223.23,91.5) ; R813.2@233.15,91.5 v1(223.23,91.5) ; 220.5,91.25 220.75,91.5 ; 220.5,91.25 220.5,91.75 ; 220.5,91.75 220.75,91.5 ; 220.75,91.5 v1(223.23,91.5)
  BOTTOM w0.5: v1(223.23,91.5) 223.65,91.08 R819.2@223.65,87.75
N00200204: D811.1 J818.2 | length 2.8
  TOP w0.5: D811.1@244.75,84.6 244.775,84.625 J818.2@247.5,84.625
N00200206: CP5.1 J808.2 L803.1 | length 13.6
  TOP w0.8: L803.1@159.45,126 159.45,122.375 159.95,121.875 J808.2@161.75,121.875
  TOP w1: L803.1@159.45,126 159.45,130.2 CP5.1@161.75,132.5
N00200210: CP9.1 J810.2 L804.1 | length 13.6
  TOP w0.5: L804.1@99.45,126 99.45,122.375 99.95,121.875 J810.2@101.75,121.875
  TOP w1: L804.1@99.45,126 99.45,130.2 CP9.1@101.75,132.5
N00200212: CP10.1 J811.2 L808.1 | length 13.6
  TOP w0.5: L808.1@99.45,112 99.45,115.625 99.95,116.125 J811.2@101.75,116.125
  TOP w1: L808.1@99.45,112 99.45,107.8 CP10.1@101.75,105.5
N00200214: C830.2 CP7.1 IC804.3 J817.1 | length 10.8
  TOP w0.8: J817.1@177.25,120.125 179.875,120.125 CP7.1@181.25,121.5 IC804.3@181.25,124.7 180.175,124.7 179.5,124.025 C830.2@178.5,124.025
N00200215: CP14.1 J813.2 L809.1 | length 13.4
  TOP w0.5: L809.1@39.45,112 39.45,115.375 40.2,116.125 J813.2@41.75,116.125
  TOP w1: L809.1@39.45,112 39.45,107.8 CP14.1@41.75,105.5
N00200216: CP13.1 J812.2 L805.1 | length 13.4
  TOP w0.5: L805.1@39.45,126 39.45,122.625 40.2,121.875 J812.2@41.75,121.875
  TOP w1: L805.1@39.45,126 39.45,130.2 CP13.1@41.75,132.5
N00200217: CP8.1 J817.2 L813.1 L814.1 L815.1 | length 29.7
  TOP w0.8: 174.95,121.125 175.7,121.875 ; 174.95,122.625 175.7,121.875 ; J817.2@177.25,121.875 175.7,121.875
  TOP w1: L813.1@174.95,126 174.95,122.625 174.95,121.125 L814.1@174.95,112 ; CP8.1@177.25,105.5 174.95,107.8 L814.1@174.95,112 ; L815.1@179.55,112 L814.1@174.95,112
N00200220: CP12.1 J820.2 L816.1 L817.1 L818.1 | length 29.7
  TOP w0.5: 114.95,121.125 115.7,121.875 ; 114.95,122.625 115.7,121.875 ; J820.2@117.25,121.875 115.7,121.875
  TOP w1: L816.1@114.95,126 114.95,122.625 114.95,121.125 L817.1@114.95,112 ; CP12.1@117.25,105.5 114.95,107.8 L817.1@114.95,112 ; L818.1@119.55,112 L817.1@114.95,112
N00200225: CP1.1 J806.2 L802.1 | length 13.4
  TOP w0.8: L802.1@219.45,126 219.45,122.75 220.325,121.875 J806.2@221.75,121.875
  TOP w1: L802.1@219.45,126 219.45,130.2 CP1.1@221.75,132.5
N00200226: CP2.1 J807.2 L806.1 | length 13.4
  TOP w0.8: L806.1@219.45,112 219.45,115.375 220.2,116.125 J807.2@221.75,116.125
  TOP w1: L806.1@219.45,112 219.45,107.8 CP2.1@221.75,105.5
N00200229: C831.2 CP11.1 IC805.3 J820.1 | length 10.8
  TOP w0.5: J820.1@117.25,120.125 119.875,120.125 CP11.1@121.25,121.5 IC805.3@121.25,124.7 120.175,124.7 119.5,124.025 C831.2@118.5,124.025
N00200231: CP16.1 J823.2 L819.1 L820.1 L821.1 | length 29.7
  TOP w0.5: 54.95,121.125 55.7,121.875 ; 54.95,122.625 55.7,121.875 ; J823.2@57.25,121.875 55.7,121.875
  TOP w1: L819.1@54.95,126 54.95,122.625 54.95,121.125 L820.1@54.95,112 ; CP16.1@57.25,105.5 54.95,107.8 L820.1@54.95,112 ; L821.1@59.55,112 L820.1@54.95,112
N00200232: C832.2 CP15.1 IC806.3 J823.1 | length 10.8
  TOP w0.5: J823.1@57.25,120.125 59.875,120.125 CP15.1@61.25,121.5 IC806.3@61.25,124.7 60.2,124.7 59.525,124.025 C832.2@58.5,124.025
N00300001: CN501.1 IC713.1 R701.1 R734.1 | length 31.5
  TOP w0.25: IC713.1@248.15,41.1 v1(248.15,42.125) ; CN501.1@249.15,59.48 251.08,59.48 v1(251.5,59.9)
  BOTTOM w0.25: R734.1@246.65,52.75 245.875,52.75 ; v1(248.15,42.125) 245.375,42.125 245.25,42.25 245.25,46.75 245.625,47.125 245.625,52.5 ; v1(251.5,59.9) R701.1@250.5,59.9 245.875,59.9 245.625,59.65 245.625,53 ; 245.625,52.5 245.625,53 ; 245.625,52.5 245.875,52.75 ; 245.625,53 245.875,52.75
N00300003: CN503.1 IC714.1 R735.1 R901.1 | length 27
  TOP w0.25: CN503.1@254.65,59.48 256.58,59.48 v1(257,59.9) ; IC714.1@255.65,41.1 v1(257.5,41.1) ; v1(255.85,49.75) v1(257.5,49.75)
  BOTTOM w0.25: v1(255.85,49.75) R735.1@255.85,50.75 ; R901.1@256,59.9 v1(257,59.9) 257.5,59.4 v1(257.5,49.75) v1(257.5,41.1)
N00300005: IC715.6 R736.1 | length 2.4
  TOP w0.25: IC715.6@252.2,48.4 v1(252.2,49.75)
  BOTTOM w0.25: R736.1@252.1,50.75 252.1,50.225 252.2,50.125 v1(252.2,49.75)
N00300006: IC715.4 R737.1 | length 6.2
  TOP w0.25: v1(249.375,48.4) IC715.4@250.3,48.4
  BOTTOM w0.25: v1(249.375,48.4) 249.375,52.5 249.625,52.75 R737.1@250.4,52.75
N00300008: C714.1 IC713.5 Q711.3 R730.2 | length 10.5
  TOP w0.25: IC713.5@248.15,38.9 v1(248.15,37.875) 248.775,37.25 251.65,37.25 ; Q711.3@251.25,38.9 251.648,38.9 251.902,38.646 251.902,37.498 ; R730.2@252.4,36 252.4,37 252.15,37.25 ; 251.65,37.25 251.9,37.5 251.902,37.498 ; 251.65,37.25 252.15,37.25 ; 251.902,37.498 252.15,37.25
  BOTTOM w0.25: v1(248.15,37.875) 248.35,38.075 C714.1@248.35,39
N00300009: Q714.6 R723.2 | length 9.1
  TOP w0.25: Q714.6@254.35,50.775 254.35,50 254.6,49.75 v1(255,49.75)
  BOTTOM w0.25: R723.2@250.4,46 250.4,46.75 250.65,47 253.875,47 255,48.125 v1(255,49.75)
N00300011: C714.2 IC713.4 R731.2 | length 6.8
  TOP w0.25: v1(246.85,37.875) IC713.4@246.85,38.9
  BOTTOM w0.25: C714.2@246.65,39 246.65,38.075 v1(246.85,37.875) 247.475,37.25 249.85,37.25 250.1,37 R731.2@250.1,36
N00300014: C715.2 IC714.4 R732.2 | length 5.9
  TOP w0.25: v1(252.625,37.875) v1(254.35,37.875) IC714.4@254.35,38.9
  BOTTOM w0.25: R732.2@252.4,36 252.4,37.025 252.625,37.25 v1(252.625,37.875) ; C715.2@254.15,39 254.15,38.075 v1(254.35,37.875)
N00300018: C712.2 C713.2 R731.1 R733.2 R738.2 | length 26.3
  TOP w0.5: v1(231.15,32.375) 231.65,32.875 240.125,32.875 241.875,34.625 v1(246.9,34.625) R733.2@246.9,36
  BOTTOM w0.5: R738.2@228.25,31.1 229.625,31.1 229.775,31.25 C713.2@231.15,31.25 ; C712.2@230.475,28.75 230.475,29.825 231.15,30.5 C713.2@231.15,31.25 ; v1(231.15,32.375) C713.2@231.15,31.25 ; v1(246.9,34.625) R731.1@246.9,36
N00300021: Q712.6 R722.2 | length 19.1
  TOP w0.25: v1(245,50.775) Q712.6@246.85,50.775
  BOTTOM w0.25: v1(245,50.775) 245,47.25 244.75,47 244.75,40.25 245,40 250.15,40 250.4,40.25 R722.2@250.4,41
N00300022: Q712.2 Q712.3 | length 0.6
  TOP w0.25: Q712.2@247.5,48.725 Q712.3@248.15,48.725
N00300023: Q713.2 R727.1 R729.2 | length 9.8
  TOP w0.25: v1(249.375,45.85) Q713.2@250.6,45.85
  BOTTOM w0.25: v1(249.375,45.85) 249.375,46.85 250.15,47.625 ; R729.2@250.4,48.75 250.4,47.875 ; R727.1@254.15,48.75 254.15,48 253.775,47.625 250.65,47.625 ; 250.15,47.625 250.4,47.875 ; 250.15,47.625 250.65,47.625 ; 250.4,47.875 250.65,47.625
N00300026: Q714.2 Q714.3 | length 0.6
  TOP w0.25: Q714.2@255,48.725 Q714.3@255.65,48.725
N00300027: C711.2 IC712.3 R723.1 R725.2 | length 6.5
  TOP w0.25: v1(253.125,46) 253.95,46 IC712.3@254.05,46.1
  BOTTOM w0.25: v1(253.125,46) R723.1@252.1,46 R725.2@252.1,43.5 C711.2@254.15,43.5
N00300029: Q711.1 R724.1 | length 9.1
  TOP w0.25: Q711.1@251.9,41.1 252.268,41.1 252.664,41.496 252.664,42.004 v1(253.172,42.512)
  Mid-Layer 1 w0.25: v1(250.6,37.875) 253.172,40.447 v1(253.172,42.512)
  BOTTOM w0.25: R724.1@250.4,39 250.4,38.075 v1(250.6,37.875)
N00300030: Q713.1 R725.1 | length 3.6
  TOP w0.25: v1(250.4,44.671) 251.521,44.671 251.9,45.05 Q713.1@251.9,45.85
  BOTTOM w0.25: R725.1@250.4,43.5 v1(250.4,44.671)
N00300031: Q711.2 R726.1 R728.2 | length 13.7
  TOP w0.25: v1(248.35,44.75) 249.156,44.75 249.616,44.29 249.616,42.084 Q711.2@250.6,41.1
  BOTTOM w0.25: R728.2@246.65,50.75 247.25,50.75 247.5,50.5 247.5,45 247.75,44.75 v1(248.35,44.75) R726.1@248.35,43.5
N00300032: IC711.4 R720.1 R726.2 | length 3.9
  TOP w0.25: IC711.4@246.55,43.4 246.65,43.5 v1(246.65,44.75)
  BOTTOM w0.25: R726.2@246.65,43.5 v1(246.65,44.75) R720.1@246.65,46
N00300035: IC712.4 R721.1 R727.2 | length 6.1
  TOP w0.25: IC712.4@254.05,43.4 v1(254.05,44.75)
  BOTTOM w0.25: v1(254.05,44.75) 254.05,45.3 254.15,45.4 R721.1@254.15,46 254.15,46.525 255.85,48.225 R727.2@255.85,48.75
N00300036: C715.1 IC714.5 Q713.3 R733.1 | length 21.3
  TOP w0.25: R733.1@250.1,36 250.1,35 250.35,34.75 253.75,34.75 254,35 254,37 254.25,37.25 255.025,37.25 v1(255.65,37.875) IC714.5@255.65,38.9 ; Q713.3@251.25,43.65 251.9,43 v1(251.9,42.5)
  BOTTOM w0.25: v1(251.9,42.5) 252.168,42.5 253.25,41.418 253.25,37.5 253.5,37.25 255.025,37.25 v1(255.65,37.875) 255.85,38.075 C715.1@255.85,39
N00300038: C710.1 R720.2 | length 2.8
  BOTTOM w0.25: R720.2@248.35,46 C710.1@248.35,48.75
N00300039: C711.1 R721.2 | length 2.5
  BOTTOM w0.25: C711.1@255.85,43.5 R721.2@255.85,46
N00300040: C710.2 IC711.3 R722.1 R724.2 | length 16.9
  TOP w0.25: IC711.3@246.55,46.1 v1(246.55,47.25)
  BOTTOM w0.25: C710.2@246.65,48.75 246.65,48.1 246.55,48 v1(246.55,47.25) 245.75,46.45 245.75,42.875 245.875,42.75 249.375,42.75 250.25,41.875 251.85,41.875 252.1,41.625 R722.1@252.1,41 R724.2@252.1,39
N00300041: C721.2 IC710.3 R823.1 R825.2 | length 6.5
  TOP w0.25: v1(238.125,46) 238.95,46 IC710.3@239.05,46.1
  BOTTOM w0.25: v1(238.125,46) R823.1@237.1,46 R825.2@237.1,43.5 C721.2@239.15,43.5
N00300044: C721.1 R821.2 | length 2.5
  BOTTOM w0.25: C721.1@240.85,43.5 R821.2@240.85,46
N00300051: C724.1 IC716.5 Q716.3 R830.2 | length 10.4
  TOP w0.25: IC716.5@233.15,38.9 v1(233.15,37.875) 233.775,37.25 236.65,37.25 ; Q716.3@236.25,38.9 236.591,38.9 236.9,38.591 236.9,37.5 ; R830.2@237.4,36 237.4,37 237.15,37.25 ; 236.65,37.25 237.15,37.25 ; 236.65,37.25 236.9,37.5 ; 236.9,37.5 237.15,37.25
  BOTTOM w0.25: v1(233.15,37.875) 233.35,38.075 C724.1@233.35,39
N00300052: CN913.1 IC814.1 R916.1 R935.1 | length 27.3
  TOP w0.25: CN913.1@225.65,59.48 227.58,59.48 v1(228,59.9) ; IC814.1@226.15,41.1 v1(228,41.1) ; v1(226.35,49.75) v1(227.875,49.75)
  BOTTOM w0.25: v1(226.35,49.75) R935.1@226.35,50.75 ; R916.1@227,59.9 v1(228,59.9) 228,59.875 227.512,59.387 227.25,59.125 227.25,53.125 227.875,52.5 v1(227.875,49.75) 227.875,41.225 v1(228,41.1)
N00300054: C724.2 IC716.4 R831.2 | length 6.8
  TOP w0.25: v1(231.85,37.875) IC716.4@231.85,38.9
  BOTTOM w0.25: C724.2@231.65,39 231.65,38.075 v1(231.85,37.875) 232.475,37.25 234.85,37.25 235.1,37 R831.2@235.1,36
N00300055: C722.2 C723.2 R831.1 R833.2 R838.2 | length 22.7
  TOP w0.5: v1(231.9,34.625) R833.2@231.9,36
  BOTTOM w0.5: R838.2@217.5,31.1 218.75,31.1 218.9,31.25 C723.2@220.4,31.25 ; C722.2@219.725,28.75 219.725,29.825 220.4,30.5 C723.2@220.4,31.25 ; R831.1@231.9,36 v1(231.9,34.625) 227.375,34.625 226.625,33.875 220.775,33.875 220.4,33.5 C723.2@220.4,31.25
N00300056: C725.1 IC717.5 Q718.3 R833.1 | length 21.5
  TOP w0.25: R833.1@235.1,36 235.1,35 235.35,34.75 238.75,34.75 239,35 239,37 239.25,37.25 240.025,37.25 v1(240.65,37.875) IC717.5@240.65,38.9 ; Q718.3@236.25,43.65 236.662,43.65 236.9,43.412 v1(236.9,42.5)
  BOTTOM w0.25: v1(236.9,42.5) 237.182,42.5 238.25,41.432 238.25,37.5 238.5,37.25 240.025,37.25 v1(240.65,37.875) 240.85,38.075 C725.1@240.85,39
N00300057: C725.2 IC717.4 R832.2 | length 5.9
  TOP w0.25: v1(237.625,37.875) v1(239.35,37.875) IC717.4@239.35,38.9
  BOTTOM w0.25: R832.2@237.4,36 237.4,37.025 237.625,37.25 v1(237.625,37.875) ; C725.2@239.15,39 239.15,38.075 v1(239.35,37.875)
N00300058: IC718.6 R836.1 | length 2.4
  TOP w0.25: IC718.6@237.2,48.4 v1(237.2,49.75)
  BOTTOM w0.25: R836.1@237.1,50.75 237.1,50.225 237.2,50.125 v1(237.2,49.75)
N00300059: IC718.4 R837.1 | length 6.2
  TOP w0.25: v1(234.375,48.4) IC718.4@235.3,48.4
  BOTTOM w0.25: v1(234.375,48.4) 234.375,52.5 234.625,52.75 R837.1@235.4,52.75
